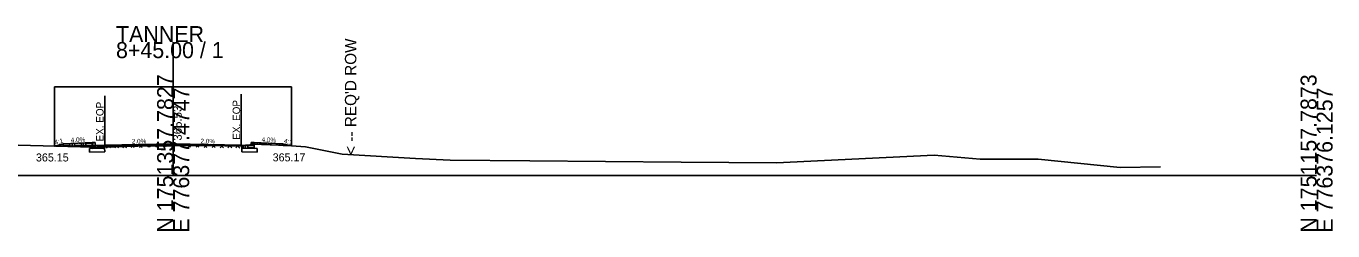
# Model space of a CAD drawing. Extents: x 774192 to 776597, y 1750236 to 1752784.
# Drawn here: x 774857.6 to 775086.2, y 1750748.9 to 1750784.7 of the extents above; entities that cross this region are included whole.
import ezdxf

# ---------------------------------------------------------------- set-up
doc = ezdxf.new("R2010")
doc.units = 0
for name, color, linetype in [('ControlPoints', 7, 'Continuous'), ('Default', 7, 'Continuous'), ('Observations', 7, 'Continuous'), ('Setups', 7, 'Continuous'), ('SHEET_BORDER_TX', 7, 'Continuous'), ('SHEET_DATE_DGN_TX', 7, 'Continuous'), ('SHEET_LOGO', 7, 'Continuous'), ('SHEET_PLOTTING_SHAPE', 7, 'Continuous'), ('SHEET_PRELIM', 7, 'Continuous'), ('SHEET_PROJ_NUMBER', 7, 'Continuous'), ('SHEET_TITLE_BLOCK_TX', 7, 'Continuous'), ('TS_BACKBONE', 7, 'Continuous'), ('TS_DIMENSIONS', 7, 'Continuous'), ('TS_SIDE_SLOPE_LT', 7, 'Continuous')]:
    doc.layers.add(name, color=color, linetype=linetype)

msp = doc.modelspace()

# ---------------------------------------------------------------- linework, layer by layer
at = {"layer": 'ControlPoints'}
msp.add_lwpolyline([(774849.66, 1750764.05), (774869.3, 1750763.55), (774870.17, 1750763.57), (774871.36, 1750763.51), (774877.17, 1750763.69), (774883.33, 1750763.73), (774895.24, 1750763.82), (774896.72, 1750763.92), (774897.33, 1750764.07), (774903.23, 1750763.79), (774906.45, 1750763.57), (774912.9, 1750762.27), (774925.7, 1750761.53), (774931.76, 1750761.26), (774945.73, 1750761.15), (774972.17, 1750760.91), (774988.88, 1750760.79), (775016.46, 1750762.14), (775024.51, 1750761.4), (775034.65, 1750761.42), (775048.97, 1750759.96), (775056.01, 1750760.11)], dxfattribs=at)
at = {"layer": 'Default'}
for p, q in [((774871.34, 1750763.69), (774883.34, 1750763.93)), ((774883.33, 1750763.93), (774895.33, 1750763.69))]:
    msp.add_line(p, q, dxfattribs=at)
at = {"layer": 'Setups'}
for p, q in [((774883.33, 1750758.57), (774883.33, 1750781.9)), ((774683.33, 1750758.57), (774883.33, 1750758.57)), ((774883.33, 1750758.57), (775083.33, 1750758.57))]:
    msp.add_line(p, q, dxfattribs=at)
at = {"layer": 'SHEET_BORDER_TX'}
for p, q in [((774868.67, 1750762.64), (774868.67, 1750763.3)), ((774871.35, 1750762.69), (774868.67, 1750762.64)), ((774895.32, 1750762.69), (774898, 1750762.64)), ((774898, 1750762.64), (774898, 1750763.3))]:
    msp.add_line(p, q, dxfattribs=at)
for points in [[(774868.67, 1750763.3), (774871.33, 1750763.36), (774871.35, 1750762.69)], [(774898, 1750763.3), (774895.33, 1750763.36), (774895.32, 1750762.69)]]:
    msp.add_lwpolyline(points, dxfattribs=at)
at = {"layer": 'SHEET_LOGO'}
for p, q in [((774871.36, 1750772.51), (774871.36, 1750763.51)), ((774895.24, 1750772.82), (774895.24, 1750763.82))]:
    msp.add_line(p, q, dxfattribs=at)
at = {"layer": 'SHEET_PLOTTING_SHAPE'}
for p, q in [((774869.17, 1750763.31), (774869.17, 1750764.31)), ((774871.33, 1750763.36), (774869.17, 1750763.31)), ((774871.33, 1750763.86), (774871.33, 1750763.36)), ((774895.33, 1750763.86), (774895.33, 1750763.36)), ((774895.33, 1750763.36), (774897.5, 1750763.31)), ((774897.5, 1750763.31), (774897.5, 1750764.31))]:
    msp.add_line(p, q, dxfattribs=at)
at = {"layer": 'SHEET_PROJ_NUMBER'}
for p, q in [((774862.6, 1750763.72), (774862.6, 1750774.1)), ((774862.6, 1750774.1), (774904, 1750774.1)), ((774904, 1750774.1), (774904, 1750763.74))]:
    msp.add_line(p, q, dxfattribs=at)
at = {"layer": 'SHEET_TITLE_BLOCK_TX'}
for p, q in [((774864.17, 1750764.11), (774862.6, 1750763.72)), ((774869.17, 1750764.31), (774864.17, 1750764.11)), ((774869.67, 1750764.32), (774869.17, 1750764.31)), ((774869.67, 1750763.82), (774869.67, 1750764.32)), ((774871.33, 1750763.86), (774869.67, 1750763.82)), ((774871.33, 1750763.86), (774883.33, 1750764.1)), ((774883.33, 1750764.1), (774895.33, 1750763.86)), ((774895.33, 1750763.86), (774897, 1750763.82)), ((774897, 1750763.82), (774897, 1750764.32)), ((774897, 1750764.32), (774897.5, 1750764.31)), ((774897.5, 1750764.31), (774902.5, 1750764.11)), ((774902.5, 1750764.11), (774904, 1750763.74))]:
    msp.add_line(p, q, dxfattribs=at)
at = {"layer": 'TS_BACKBONE'}
for p, q in [((774863, 1750763.82), (774863.17, 1750763.82)), ((774863.27, 1750763.89), (774863.27, 1750763.73)), ((774863.27, 1750763.73), (774863.27, 1750763.7)), ((774863.67, 1750763.99), (774863.67, 1750763.74)), ((774863.67, 1750763.74), (774863.67, 1750763.69)), ((774864.07, 1750764.09), (774864.07, 1750763.74)), ((774864.07, 1750763.74), (774864.07, 1750763.68)), ((774864.17, 1750763.82), (774865.17, 1750763.82)), ((774865.27, 1750764.16), (774865.27, 1750763.76)), ((774865.27, 1750763.76), (774865.27, 1750763.65)), ((774865.67, 1750764.17), (774865.67, 1750763.77)), ((774865.67, 1750763.77), (774865.67, 1750763.64)), ((774866.07, 1750764.19), (774866.07, 1750763.77)), ((774866.07, 1750763.77), (774866.07, 1750763.63)), ((774866.17, 1750763.82), (774867.17, 1750763.82)), ((774866.84, 1750764.22), (774867.17, 1750764.22)), ((774867.27, 1750764.24), (774867.27, 1750763.79)), ((774867.27, 1750763.79), (774867.27, 1750763.6)), ((774867.67, 1750764.25), (774867.67, 1750763.8)), ((774867.67, 1750763.8), (774867.67, 1750763.59)), ((774868.07, 1750764.27), (774868.07, 1750763.8)), ((774868.07, 1750763.8), (774868.07, 1750763.58)), ((774868.17, 1750764.22), (774869.17, 1750764.22)), ((774868.17, 1750763.82), (774869.17, 1750763.82)), ((774869.27, 1750764.31), (774869.27, 1750763.82)), ((774869.27, 1750763.82), (774869.27, 1750763.32)), ((774869.67, 1750763.82), (774869.67, 1750763.32)), ((774870.07, 1750763.83), (774870.07, 1750763.33)), ((774870.17, 1750763.82), (774871.17, 1750763.82)), ((774870.17, 1750763.42), (774871.17, 1750763.42)), ((774871.27, 1750763.86), (774871.27, 1750763.36)), ((774871.67, 1750763.36), (774872.18, 1750763.87)), ((774871.88, 1750763.87), (774872.37, 1750763.38)), ((774873.11, 1750763.39), (774873.62, 1750763.9)), ((774873.27, 1750763.9), (774873.76, 1750763.41)), ((774874.55, 1750763.42), (774875.06, 1750763.93)), ((774874.66, 1750763.92), (774875.15, 1750763.43)), ((774875.99, 1750763.45), (774876.5, 1750763.96)), ((774876.04, 1750763.95), (774876.53, 1750763.46)), ((774877.43, 1750763.98), (774877.92, 1750763.49)), ((774877.44, 1750763.48), (774877.95, 1750763.99)), ((774878.82, 1750764.01), (774879.31, 1750763.52)), ((774878.88, 1750763.51), (774879.39, 1750764.02)), ((774880.2, 1750764.03), (774880.69, 1750763.54)), ((774880.32, 1750763.54), (774880.83, 1750764.05)), ((774881.59, 1750764.06), (774882.08, 1750763.57)), ((774881.77, 1750763.57), (774882.28, 1750764.08)), ((774882.97, 1750764.09), (774883.47, 1750763.59)), ((774883.21, 1750763.59), (774883.71, 1750764.09)), ((774884.4, 1750764.08), (774884.91, 1750763.57)), ((774884.6, 1750763.57), (774885.09, 1750764.06)), ((774885.85, 1750764.05), (774886.36, 1750763.54)), ((774885.99, 1750763.54), (774886.48, 1750764.03)), ((774887.29, 1750764.02), (774887.8, 1750763.51)), ((774887.37, 1750763.52), (774887.86, 1750764.01)), ((774888.73, 1750763.99), (774889.24, 1750763.48)), ((774888.76, 1750763.49), (774889.25, 1750763.98)), ((774890.15, 1750763.46), (774890.64, 1750763.95)), ((774890.18, 1750763.96), (774890.69, 1750763.45)), ((774891.53, 1750763.43), (774892.02, 1750763.92)), ((774891.62, 1750763.93), (774892.13, 1750763.42)), ((774892.92, 1750763.41), (774893.41, 1750763.9)), ((774893.06, 1750763.9), (774893.57, 1750763.39)), ((774894.31, 1750763.38), (774894.8, 1750763.87)), ((774894.5, 1750763.87), (774895.02, 1750763.36)), ((774895.33, 1750763.82), (774895.5, 1750763.82)), ((774895.33, 1750763.42), (774895.5, 1750763.42)), ((774895.61, 1750763.85), (774895.61, 1750763.35)), ((774896.01, 1750763.84), (774896.01, 1750763.34)), ((774896.41, 1750763.84), (774896.41, 1750763.34)), ((774896.5, 1750763.82), (774897.5, 1750763.82)), ((774896.5, 1750763.42), (774897.5, 1750763.42)), ((774897, 1750764.32), (774897, 1750764.31)), ((774897, 1750764.22), (774897.5, 1750764.22)), ((774897.4, 1750764.32), (774897.4, 1750764.31)), ((774897.4, 1750763.32), (774897.4, 1750763.32)), ((774897.61, 1750764.31), (774897.61, 1750764.05)), ((774898.01, 1750764.29), (774898.01, 1750764.04)), ((774898.41, 1750764.28), (774898.41, 1750764.02)), ((774898.5, 1750764.22), (774899.5, 1750764.22)), ((774899.61, 1750764.23), (774899.61, 1750763.96)), ((774900.01, 1750764.21), (774900.01, 1750763.94)), ((774900.41, 1750764.2), (774900.41, 1750763.92)), ((774901.61, 1750764.15), (774901.61, 1750763.87)), ((774902.01, 1750764.13), (774902.01, 1750763.85)), ((774902.41, 1750764.12), (774902.41, 1750763.83)), ((774902.58, 1750763.82), (774903.5, 1750763.82)), ((774903.61, 1750763.84), (774903.61, 1750763.77))]:
    msp.add_line(p, q, dxfattribs=at)
at = {"layer": 'TS_SIDE_SLOPE_LT'}
msp.add_line((774869.67, 1750763.82), (774862.6, 1750763.72), dxfattribs=at)

# ---------------------------------------------------------------- texts
at = {"layer": 'Observations'}
for s, p in [('365.15', (774859.33, 1750761.02)), ('365.17', (774900.73, 1750761.04))]:
    msp.add_text(s, height=1.4, dxfattribs=at).set_placement(p)
at = {"layer": 'Setups'}
for s, p in [('TANNER', (774873.33, 1750781.9)), ('8+45.00 / 1', (774873.33, 1750779.1))]:
    msp.add_text(s, height=2.8, dxfattribs=at).set_placement(p)
for s, p in [('N 1751357.7827', (774883.33, 1750748.57)), ('N 1751157.7873', (775083.33, 1750748.57)), ('E 776377.4747', (774886.13, 1750748.57)), ('E 776376.1257', (775086.13, 1750748.57))]:
    msp.add_text(s, height=2.8, rotation=90, dxfattribs=at).set_placement(p)
at = {"layer": 'SHEET_DATE_DGN_TX'}
for s, rotation, p in [('4:1', 14.0362, (774862.67, 1750763.95)), ('4.0%', 2.2906, (774865.44, 1750764.37)), ('2.0%', 1.1458, (774876.11, 1750764.15)), ('2.0%', 358.8542, (774888.11, 1750764.2)), ('4.0%', 357.7094, (774898.79, 1750764.46)), ('4:1', 345.9638, (774902.64, 1750764.29))]:
    msp.add_text(s, height=0.8, rotation=rotation, dxfattribs=at).set_placement(p)
at = {"layer": 'SHEET_LOGO'}
for p in [(774895.04, 1750764.82), (774871.16, 1750764.51)]:
    msp.add_text('EX. EOP', height=1.3, rotation=90, dxfattribs=at).set_placement(p)
at = {"layer": 'SHEET_PRELIM'}
msp.add_text(' 365.53', height=1.5, rotation=90, dxfattribs=at).set_placement((774884.83, 1750764.1))
at = {"layer": 'TS_DIMENSIONS'}
msp.add_text("< -- REQ'D ROW", height=2, rotation=90, dxfattribs=at).set_placement((774915.37, 1750762.19))

doc.saveas('drawing.dxf')
